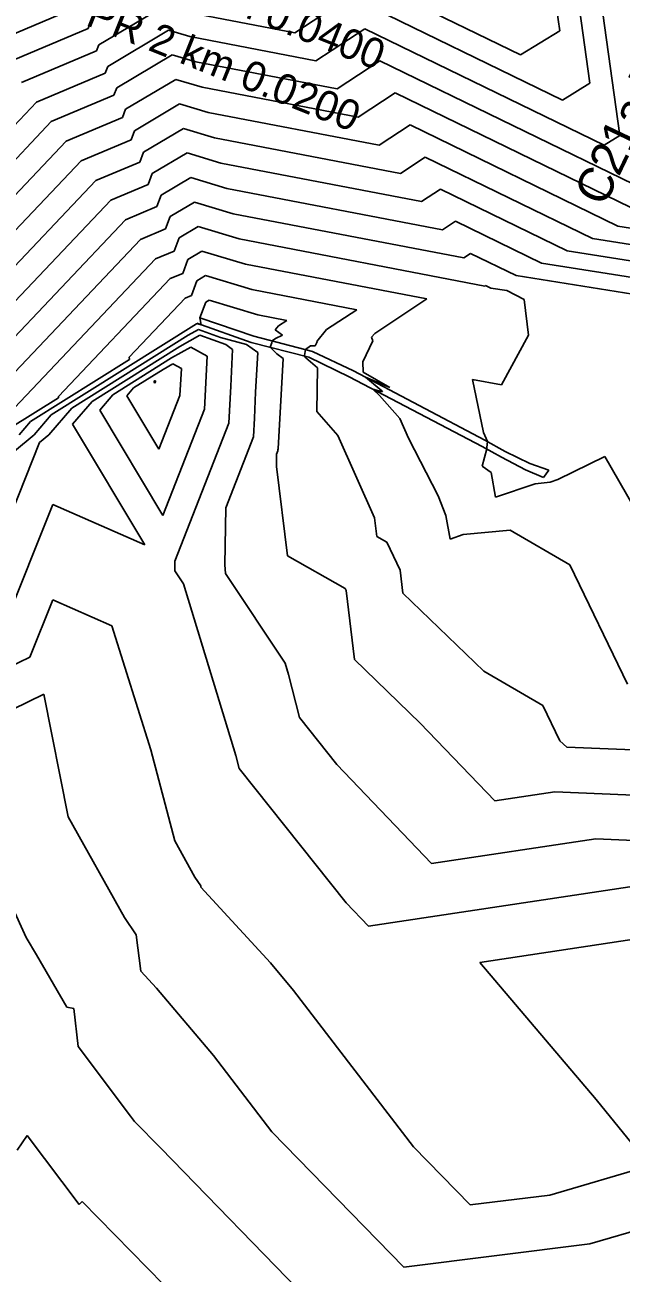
# Model space of a CAD drawing. Extents: x -549394 to -546608, y -1037055 to -1033629.
# Drawn here: x -548647.4 to -548467.8, y -1034298.9 to -1033923 of the extents above; entities that cross this region are included whole.
import ezdxf

# ---------------------------------------------------------------- set-up
doc = ezdxf.new("R2010")
doc.units = 0
for name, color, linetype in [('HLAVNI_VRST', 7, 'Continuous'), ('HRANA_L', 7, 'Continuous'), ('NORM_VRST', 7, 'Continuous'), ('x_popis_pricne_rezy_C21a', 7, 'Continuous'), ('x_popis_velky_C21a', 7, 'Continuous')]:
    doc.layers.add(name, color=color, linetype=linetype)

msp = doc.modelspace()

# ---------------------------------------------------------------- linework, layer by layer
at = {"layer": 'HLAVNI_VRST'}
for p, q in [((-548490.833895, -1033892.034012), (-548486.312771, -1033924.790682)), ((-548498.073314, -1033932.014031), (-548554.071999, -1033904.761011)), ((-548628.373693, -1033924.063589), (-548652.864545, -1033934.367749)), ((-548627.803158, -1033922.533449), (-548628.373693, -1033924.063589)), ((-548486.312771, -1033924.790682), (-548498.073314, -1033932.014031)), ((-548600.783034, -1033946.756375), (-548614.382105, -1033954.829188)), ((-548592.148146, -1033949.352685), (-548600.783034, -1033946.756375)), ((-548540.655675, -1033959.222434), (-548592.148146, -1033949.352685)), ((-548531.351368, -1033953.107008), (-548540.655675, -1033959.222434)), ((-548468.798144, -1033983.549941), (-548531.351368, -1033953.107008)), ((-548615.406888, -1033957.577593), (-548630.478182, -1033963.918615)), ((-548614.382105, -1033954.829188), (-548615.406888, -1033957.577593)), ((-548630.478182, -1033963.918615), (-548664.244255, -1033999.570355)), ((-548595.204583, -1033983.707716), (-548600.961053, -1033987.124927)), ((-548582.805577, -1033987.435809), (-548595.204583, -1033983.707716)), ((-548451.078973, -1033986.353764), (-548468.798144, -1033983.549941)), ((-548600.961053, -1033987.124927), (-548602.440083, -1033991.091598)), ((-548508.866518, -1034001.607976), (-548582.805577, -1033987.435809)), ((-548602.440083, -1033991.091598), (-548608.091818, -1033993.469481)), ((-548608.091818, -1033993.469481), (-548657.96766, -1034046.130638)), ((-548508.630736, -1034001.453004), (-548508.866518, -1034001.607976)), ((-548507.045567, -1034002.224462), (-548508.630736, -1034001.453004)), ((-548502.274967, -1034002.979346), (-548507.045567, -1034002.224462)), ((-548497.028333, -1034005.698333), (-548502.274967, -1034002.979346)), ((-548495.743902, -1034016.375854), (-548497.028333, -1034005.698333)), ((-548594.7162, -1034016.4408), (-548600.730965, -1034019.837795)), ((-548586.903582, -1034019.268358), (-548594.7162, -1034016.4408)), ((-548503.801111, -1034031.374444), (-548495.743902, -1034016.375854)), ((-548600.730965, -1034019.837795), (-548627.097363, -1034036.364388)), ((-548584.852373, -1034020.685085), (-548586.903582, -1034019.268358)), ((-548585.343887, -1034031.766844), (-548584.852373, -1034020.685085)), ((-548512.553077, -1034029.728974), (-548503.801111, -1034031.374444)), ((-548509.28, -1034045.683636), (-548512.553077, -1034029.728974)), ((-548585.938839, -1034042.902776), (-548585.343887, -1034031.766844)), ((-548627.097363, -1034036.364388), (-548633.015452, -1034043.246436)), ((-548633.015452, -1034043.246436), (-548611.262444, -1034079.530111)), ((-548602.206396, -1034084.51009), (-548585.938839, -1034042.902776)), ((-548508.10875, -1034048.48), (-548509.28, -1034045.683636)), ((-548508.307586, -1034050.197011), (-548508.10875, -1034048.48)), ((-548509.678349, -1034055.82422), (-548508.271111, -1034050.669722)), ((-548508.271111, -1034050.669722), (-548508.307586, -1034050.197011)), ((-548506.9755, -1034057.765), (-548509.678349, -1034055.82422)), ((-548472.695765, -1034052.912118), (-548486.924615, -1034059.835769)), ((-548457.036154, -1034080.402051), (-548472.695765, -1034052.912118)), ((-548505.662222, -1034065.251111), (-548506.9755, -1034057.765)), ((-548486.924615, -1034059.835769), (-548489.156957, -1034060.703478)), ((-548493.745556, -1034061.14), (-548505.662222, -1034065.251111)), ((-548489.156957, -1034060.703478), (-548493.745556, -1034061.14)), ((-548638.983878, -1034067.36403), (-548653.489501, -1034103.858004)), ((-548611.262444, -1034079.530111), (-548638.983878, -1034067.36403)), ((-548602.244378, -1034087.013838), (-548602.206396, -1034084.51009)), ((-548602.220848, -1034087.383939), (-548602.244378, -1034087.013838)), ((-548599.614032, -1034091.312177), (-548602.220848, -1034087.383939)), ((-548583.865933, -1034143.0094), (-548599.614032, -1034091.312177)), ((-548582.86797, -1034146.920305), (-548583.865933, -1034143.0094)), ((-548550.63627, -1034187.342378), (-548582.86797, -1034146.920305)), ((-548463.15334, -1034182.22053), (-548543.89, -1034194.389343)), ((-548543.89, -1034194.389343), (-548550.63627, -1034187.342378))]:
    msp.add_line(p, q, dxfattribs=at)
at = {"layer": 'HRANA_L'}
for p, q in [((-548579.25, -1034018.6), (-548595.61, -1034012.8)), ((-548594.66, -1034011.2), (-548578.47, -1034016.69)), ((-548578.47, -1034016.69), (-548560.81, -1034021.29)), ((-548561.83, -1034023.04), (-548579.25, -1034018.6)), ((-548548.37, -1034027.11), (-548560.81, -1034021.29)), ((-548549.74, -1034028.97), (-548561.83, -1034023.04)), ((-548549.74, -1034028.97), (-548509.65, -1034049.9)), ((-548508.87, -1034048.06), (-548548.37, -1034027.11)), ((-548508.87, -1034048.06), (-548502.78, -1034051.42)), ((-548503.81, -1034053.16), (-548509.65, -1034049.9)), ((-548502.78, -1034051.42), (-548495.34, -1034055.08)), ((-548496.63, -1034056.94), (-548503.81, -1034053.16)), ((-548495.34, -1034055.08), (-548489.59, -1034057.06)), ((-548491.15, -1034059.3), (-548496.63, -1034056.94)), ((-548489.59, -1034057.06), (-548491.15, -1034059.3))]:
    msp.add_line(p, q, dxfattribs=at)
at = {"layer": 'NORM_VRST'}
for p, q in [((-548482.367044, -1033903.57614), (-548477.267031, -1033940.527004)), ((-548549.527873, -1033914.43021), (-548566.087, -1033925.314)), ((-548485.506453, -1033945.587674), (-548549.527873, -1033914.43021)), ((-548473.900193, -1033915.118267), (-548468.221291, -1033956.263327)), ((-548630.967054, -1033917.360788), (-548657.341818, -1033928.457576)), ((-548605.245794, -1033917.195303), (-548625.118947, -1033928.992596)), ((-548566.087, -1033925.314), (-548599.622202, -1033918.886186)), ((-548544.983746, -1033924.09941), (-548559.729169, -1033933.791108)), ((-548472.939593, -1033959.161318), (-548544.983746, -1033924.09941)), ((-548604.130104, -1033924.585571), (-548622.434737, -1033935.451744)), ((-548597.753688, -1033926.502811), (-548604.130104, -1033924.585571)), ((-548559.729169, -1033933.791108), (-548597.753688, -1033926.502811)), ((-548625.780332, -1033930.76639), (-548648.387273, -1033940.277922)), ((-548625.118947, -1033928.992596), (-548625.780332, -1033930.76639)), ((-548603.014414, -1033931.975839), (-548619.750526, -1033941.910892)), ((-548595.885174, -1033934.119436), (-548603.014414, -1033931.975839)), ((-548622.434737, -1033935.451744), (-548623.186971, -1033937.469191)), ((-548553.371337, -1033942.268217), (-548595.885174, -1033934.119436)), ((-548540.43962, -1033933.768609), (-548553.371337, -1033942.268217)), ((-548460.372733, -1033972.734961), (-548540.43962, -1033933.768609)), ((-548623.186971, -1033937.469191), (-548643.91, -1033946.188095)), ((-548601.898724, -1033939.366107), (-548617.066316, -1033948.37004)), ((-548594.01666, -1033941.73606), (-548601.898724, -1033939.366107)), ((-548619.750526, -1033941.910892), (-548620.59361, -1033944.171992)), ((-548547.013506, -1033950.745325), (-548594.01666, -1033941.73606)), ((-548477.267031, -1033940.527004), (-548485.506453, -1033945.587674)), ((-548643.91, -1033946.188095), (-548668.010213, -1033971.634184)), ((-548620.59361, -1033944.171992), (-548639.432727, -1033952.098268)), ((-548535.895494, -1033943.437808), (-548547.013506, -1033950.745325)), ((-548461.14866, -1033979.815037), (-548535.895494, -1033943.437808)), ((-548617.066316, -1033948.37004), (-548618.000249, -1033950.874793)), ((-548639.432727, -1033952.098268), (-548666.754894, -1033980.946241)), ((-548618.000249, -1033950.874793), (-548634.955455, -1033958.008442)), ((-548599.667344, -1033954.146643), (-548611.697895, -1033961.288336)), ((-548590.279632, -1033956.96931), (-548599.667344, -1033954.146643)), ((-548634.955455, -1033958.008442), (-548665.499574, -1033990.258298)), ((-548534.297843, -1033967.699542), (-548590.279632, -1033956.96931)), ((-548468.221291, -1033956.263327), (-548472.939593, -1033959.161318)), ((-548611.697895, -1033961.288336), (-548612.813527, -1033964.280394)), ((-548598.551653, -1033961.536912), (-548609.013684, -1033967.747484)), ((-548588.411118, -1033964.585935), (-548598.551653, -1033961.536912)), ((-548612.813527, -1033964.280394), (-548626.000909, -1033969.828788)), ((-548527.940012, -1033976.176651), (-548588.411118, -1033964.585935)), ((-548526.807241, -1033962.776207), (-548534.297843, -1033967.699542)), ((-548476.447629, -1033987.284845), (-548526.807241, -1033962.776207)), ((-548609.013684, -1033967.747484), (-548610.220166, -1033970.983195)), ((-548597.435963, -1033968.92718), (-548606.329474, -1033974.206632)), ((-548586.542605, -1033972.202559), (-548597.435963, -1033968.92718)), ((-548626.000909, -1033969.828788), (-548662.988936, -1034008.882411)), ((-548610.220166, -1033970.983195), (-548621.523636, -1033975.738961)), ((-548521.582181, -1033984.653759), (-548586.542605, -1033972.202559)), ((-548522.263115, -1033972.445406), (-548527.940012, -1033976.176651)), ((-548484.097113, -1033991.01975), (-548522.263115, -1033972.445406)), ((-548621.523636, -1033975.738961), (-548661.733617, -1034018.194468)), ((-548606.329474, -1033974.206632), (-548607.626805, -1033977.685996)), ((-548596.320273, -1033976.317448), (-548603.645263, -1033980.665779)), ((-548584.674091, -1033979.819184), (-548596.320273, -1033976.317448)), ((-548607.626805, -1033977.685996), (-548617.046364, -1033981.649134)), ((-548603.645263, -1033980.665779), (-548605.033444, -1033984.388797)), ((-548515.224349, -1033993.130867), (-548584.674091, -1033979.819184)), ((-548617.046364, -1033981.649134), (-548660.478298, -1034027.506525)), ((-548605.033444, -1033984.388797), (-548612.569091, -1033987.559307)), ((-548517.718989, -1033982.114605), (-548521.582181, -1033984.653759)), ((-548491.746598, -1033994.754654), (-548517.718989, -1033982.114605)), ((-548612.569091, -1033987.559307), (-548659.222979, -1034036.818582)), ((-548448.054259, -1033991.777719), (-548476.447629, -1033987.284845)), ((-548594.088893, -1033991.097984), (-548598.276842, -1033993.584075)), ((-548580.937063, -1033995.052433), (-548594.088893, -1033991.097984)), ((-548513.174863, -1033991.783805), (-548515.224349, -1033993.130867)), ((-548499.396082, -1033998.489558), (-548513.174863, -1033991.783805)), ((-548445.029544, -1033997.201673), (-548484.097113, -1033991.01975)), ((-548598.276842, -1033993.584075), (-548599.846722, -1033997.794398)), ((-548526.363538, -1034005.512738), (-548580.937063, -1033995.052433)), ((-548442.004829, -1034002.625627), (-548491.746598, -1033994.754654)), ((-548603.614545, -1033999.379654), (-548637.266061, -1034034.910438)), ((-548599.846722, -1033997.794398), (-548603.614545, -1033999.379654)), ((-548592.973203, -1033998.488252), (-548595.592632, -1034000.043223)), ((-548579.068549, -1034002.669058), (-548592.973203, -1033998.488252)), ((-548457.928562, -1034005.051242), (-548499.396082, -1033998.489558)), ((-548595.592632, -1034000.043223), (-548597.253361, -1034004.497199)), ((-548547.425077, -1034008.734277), (-548579.068549, -1034002.669058)), ((-548599.137273, -1034005.289827), (-548615.96303, -1034023.055219)), ((-548597.253361, -1034004.497199), (-548599.137273, -1034005.289827)), ((-548592.908421, -1034006.502371), (-548594.66, -1034011.2)), ((-548591.857512, -1034005.87852), (-548592.908421, -1034006.502371)), ((-548577.200035, -1034010.285683), (-548591.857512, -1034005.87852)), ((-548542.043074, -1034015.879576), (-548526.363538, -1034005.512738)), ((-548568.486615, -1034011.955815), (-548577.200035, -1034010.285683)), ((-548556.516572, -1034014.7453), (-548547.425077, -1034008.734277)), ((-548595.734902, -1034012.971654), (-548639.504863, -1034040.406888)), ((-548595.1522, -1034014.6648), (-548598.232933, -1034016.404724)), ((-548595.5882, -1034012.8888), (-548595.734902, -1034012.971654)), ((-548595.270383, -1034013.003825), (-548595.5882, -1034012.8888)), ((-548594.269016, -1034013.27541), (-548595.270383, -1034013.003825)), ((-548588.478033, -1034017.080328), (-548595.1522, -1034014.6648)), ((-548594.66, -1034011.2), (-548594.269016, -1034013.27541)), ((-548594.66, -1034011.2), (-548594.66, -1034011.2)), ((-548594.66, -1034011.2), (-548594.66, -1034011.2)), ((-548594.66, -1034011.2), (-548594.66, -1034011.2)), ((-548594.66, -1034011.2), (-548594.66, -1034011.2)), ((-548594.66, -1034011.2), (-548594.66, -1034011.2)), ((-548571.972903, -1034014.798065), (-548570.990071, -1034013.611025)), ((-548570.990071, -1034013.611025), (-548568.486615, -1034011.955815)), ((-548559.441321, -1034018.277736), (-548556.516572, -1034014.7453)), ((-548598.232933, -1034016.404724), (-548633.301113, -1034038.385638)), ((-548580.667377, -1034019.198689), (-548588.478033, -1034017.080328)), ((-548573.054615, -1034018.756568), (-548572.919714, -1034018.135714)), ((-548572.919714, -1034018.135714), (-548571.948014, -1034017.380426)), ((-548569.819136, -1034016.368395), (-548571.972903, -1034014.798065)), ((-548571.948014, -1034017.380426), (-548569.819136, -1034016.368395)), ((-548559.966, -1034019.613333), (-548559.396963, -1034018.420593)), ((-548559.396963, -1034018.420593), (-548559.441321, -1034018.277736)), ((-548545.577, -1034024.401), (-548542.589556, -1034018.139111)), ((-548542.950755, -1034016.975849), (-548542.043074, -1034015.879576)), ((-548542.589556, -1034018.139111), (-548542.950755, -1034016.975849)), ((-548597.457597, -1034020.011318), (-548603.228996, -1034023.270866)), ((-548592.462077, -1034022.688792), (-548597.457597, -1034020.011318)), ((-548577.223636, -1034021.648325), (-548580.667377, -1034019.198689)), ((-548577.907541, -1034033.562623), (-548577.223636, -1034021.648325)), ((-548573.511647, -1034020.062588), (-548573.054615, -1034018.756568)), ((-548571.506552, -1034022.062989), (-548573.511647, -1034020.062588)), ((-548569.587273, -1034023.42823), (-548571.506552, -1034022.062989)), ((-548563.208462, -1034022.513964), (-548562.828286, -1034020.764286)), ((-548562.828286, -1034020.764286), (-548561.362941, -1034019.625294)), ((-548561.362941, -1034019.625294), (-548559.966, -1034019.613333)), ((-548615.885342, -1034023.73476), (-548645.708613, -1034042.428138)), ((-548603.228996, -1034023.270866), (-548620.893613, -1034034.343138)), ((-548615.96303, -1034023.055219), (-548615.885342, -1034023.73476)), ((-548602.798682, -1034025.050078), (-548605.727028, -1034026.703937)), ((-548600.26401, -1034026.408599), (-548602.798682, -1034025.050078)), ((-548593.31876, -1034038.723642), (-548592.462077, -1034022.688792)), ((-548571.147978, -1034050.617268), (-548569.587273, -1034023.42823)), ((-548563.264588, -1034022.674353), (-548563.208462, -1034022.513964)), ((-548562.739157, -1034023.198554), (-548563.264588, -1034022.674353)), ((-548559.23245, -1034026.260199), (-548562.739157, -1034023.198554)), ((-548545.481818, -1034027.584545), (-548545.577, -1034024.401)), ((-548605.727028, -1034026.703937), (-548614.689863, -1034032.321888)), ((-548600.698681, -1034034.544508), (-548600.26401, -1034026.408599)), ((-548559.501243, -1034039.393729), (-548559.23245, -1034026.260199)), ((-548537.43, -1034032.21), (-548545.481818, -1034027.584545)), ((-548539.857, -1034033.138), (-548544.779091, -1034029.014545)), ((-548544.779091, -1034029.014545), (-548537.43, -1034032.21)), ((-548614.689863, -1034032.321888), (-548616.701622, -1034034.66133)), ((-548608.486113, -1034030.300638), (-548608.544707, -1034030.368777)), ((-548608.544707, -1034030.368777), (-548608.263392, -1034030.838007)), ((-548608.225059, -1034030.137008), (-548608.486113, -1034030.300638)), ((-548608.263392, -1034030.838007), (-548608.078602, -1034030.365374)), ((-548608.139767, -1034030.088837), (-548608.225059, -1034030.137008)), ((-548608.065942, -1034030.128406), (-548608.139767, -1034030.088837)), ((-548608.078602, -1034030.365374), (-548608.065942, -1034030.128406)), ((-548578.254186, -1034041.37814), (-548577.907541, -1034033.562623)), ((-548540.574595, -1034034.598649), (-548542.595248, -1034032.700099)), ((-548542.595248, -1034032.700099), (-548539.68172, -1034033.460645)), ((-548539.68172, -1034033.460645), (-548539.857, -1034033.138)), ((-548537.43, -1034032.21), (-548537.43, -1034032.21)), ((-548537.43, -1034032.21), (-548537.43, -1034032.21)), ((-548537.43, -1034032.21), (-548537.43, -1034032.21)), ((-548537.43, -1034032.21), (-548537.43, -1034032.21)), ((-548637.227808, -1034035.245034), (-548651.912363, -1034044.449387)), ((-548637.266061, -1034034.910438), (-548637.227808, -1034035.245034)), ((-548620.893613, -1034034.343138), (-548624.858537, -1034038.953883)), ((-548616.701622, -1034034.66133), (-548607.043112, -1034050.771573)), ((-548607.043112, -1034050.771573), (-548600.698681, -1034034.544508)), ((-548534.443411, -1034041.510421), (-548540.574595, -1034034.598649)), ((-548639.504863, -1034040.406888), (-548644.649057, -1034046.388986)), ((-548633.301113, -1034038.385638), (-548640.177358, -1034046.38191)), ((-548624.858537, -1034038.953883), (-548605.822832, -1034070.70514)), ((-548605.822832, -1034070.70514), (-548593.31876, -1034038.723642)), ((-548553.092944, -1034046.617897), (-548559.501243, -1034039.393729)), ((-548645.708613, -1034042.428138), (-548649.120755, -1034046.396061)), ((-548578.558917, -1034047.081909), (-548578.254186, -1034041.37814)), ((-548531.830612, -1034047.387755), (-548534.443411, -1034041.510421)), ((-548644.649057, -1034046.388986), (-548657.814424, -1034057.344029)), ((-548640.177358, -1034046.38191), (-548642.976295, -1034048.710935)), ((-548586.891081, -1034068.392973), (-548578.558917, -1034047.081909)), ((-548542.056121, -1034071.444569), (-548553.092944, -1034046.617897)), ((-548522.89568, -1034064.85056), (-548531.830612, -1034047.387755)), ((-548642.976295, -1034048.710935), (-548661.105028, -1034094.320111)), ((-548571.631622, -1034055.957838), (-548571.575766, -1034052.275856)), ((-548571.575766, -1034052.275856), (-548571.178996, -1034051.261043)), ((-548571.178996, -1034051.261043), (-548571.164485, -1034050.989435)), ((-548571.164485, -1034050.989435), (-548571.147978, -1034050.617268)), ((-548568.275098, -1034082.835294), (-548571.631622, -1034055.957838)), ((-548520.591042, -1034070.754583), (-548522.89568, -1034064.85056)), ((-548587.152486, -1034085.624649), (-548586.891081, -1034068.392973)), ((-548519.347407, -1034077.843704), (-548520.591042, -1034070.754583)), ((-548541.353529, -1034077.070588), (-548542.056121, -1034071.444569)), ((-548538.348605, -1034078.778837), (-548541.353529, -1034077.070588)), ((-548515.375185, -1034076.473333), (-548519.347407, -1034077.843704)), ((-548501.19, -1034075.123871), (-548515.375185, -1034076.473333)), ((-548483.218324, -1034085.595027), (-548501.19, -1034075.123871)), ((-548534.348228, -1034087.193797), (-548538.348605, -1034078.778837)), ((-548586.990545, -1034088.171818), (-548587.152486, -1034085.624649)), ((-548550.961008, -1034092.678062), (-548568.275098, -1034082.835294)), ((-548465.868146, -1034121.489536), (-548483.218324, -1034085.595027)), ((-548569.049516, -1034115.207339), (-548586.990545, -1034088.171818)), ((-548533.511429, -1034094.134898), (-548534.348228, -1034087.193797)), ((-548550.664684, -1034093.301392), (-548550.961008, -1034092.678062)), ((-548548.154286, -1034114.124694), (-548550.664684, -1034093.301392)), ((-548639.00289, -1034096.109278), (-548645.873974, -1034113.395896)), ((-548621.22289, -1034103.91237), (-548639.00289, -1034096.109278)), ((-548509.168261, -1034117.64), (-548533.511429, -1034094.134898)), ((-548609.424082, -1034141.284082), (-548621.22289, -1034103.91237)), ((-548645.873974, -1034113.395896), (-548670.80904, -1034125.463437)), ((-548568.019267, -1034118.5894), (-548569.049516, -1034115.207339)), ((-548528.342692, -1034133.254231), (-548548.154286, -1034114.124694)), ((-548564.700457, -1034131.595431), (-548568.019267, -1034118.5894)), ((-548491.42373, -1034127.978811), (-548509.168261, -1034117.64)), ((-548641.66, -1034124.58), (-548668.722353, -1034137.677059)), ((-548634.40326, -1034161.462044), (-548641.66, -1034124.58)), ((-548486.291987, -1034138.595497), (-548491.42373, -1034127.978811)), ((-548553.398432, -1034145.769405), (-548564.700457, -1034131.595431)), ((-548505.89, -1034156.707682), (-548528.342692, -1034133.254231)), ((-548484.158636, -1034140.506818), (-548486.291987, -1034138.595497)), ((-548602.280704, -1034168.747465), (-548609.424082, -1034141.284082)), ((-548422.375745, -1034143.071602), (-548484.158636, -1034140.506818)), ((-548524.89, -1034175.548512), (-548553.398432, -1034145.769405)), ((-548647.017907, -1034197.785814), (-548667.921356, -1034152.071525)), ((-548487.739898, -1034153.972057), (-548505.89, -1034156.707682)), ((-548424.65234, -1034156.591001), (-548487.739898, -1034153.972057)), ((-548617.382208, -1034191.767403), (-548634.40326, -1034161.462044)), ((-548596.185556, -1034179.637778), (-548602.280704, -1034168.747465)), ((-548475.446619, -1034168.096293), (-548524.89, -1034175.548512)), ((-548426.928936, -1034170.110401), (-548475.446619, -1034168.096293)), ((-548594.407674, -1034182.26907), (-548596.185556, -1034179.637778)), ((-548594.355113, -1034182.69203), (-548594.407674, -1034182.26907)), ((-548573.46303, -1034205.492121), (-548594.355113, -1034182.69203)), ((-548613.849535, -1034196.995814), (-548617.382208, -1034191.767403)), ((-548643.929429, -1034203.011524), (-548647.017907, -1034197.785814)), ((-548612.482932, -1034207.992782), (-548613.849535, -1034196.995814)), ((-548450.860061, -1034196.344766), (-548510.405594, -1034205.319604)), ((-548634.8, -1034218.773333), (-548643.929429, -1034203.011524)), ((-548566.447159, -1034213.77125), (-548573.46303, -1034205.492121)), ((-548510.405594, -1034205.319604), (-548475.28601, -1034246.589615)), ((-548607.786263, -1034213.118384), (-548612.482932, -1034207.992782)), ((-548590.602462, -1034233.39625), (-548607.786263, -1034213.118384)), ((-548530.299444, -1034260.916111), (-548566.447159, -1034213.77125)), ((-548632.629216, -1034219.173137), (-548634.8, -1034218.773333)), ((-548631.360922, -1034230.662979), (-548632.629216, -1034219.173137)), ((-548615.632667, -1034251.622667), (-548631.360922, -1034230.662979)), ((-548572.992037, -1034256.364259), (-548590.602462, -1034233.39625)), ((-548475.28601, -1034246.589615), (-548459.160435, -1034266.605362)), ((-548614.383594, -1034253.288828), (-548615.632667, -1034251.622667)), ((-548614.338015, -1034253.244682), (-548614.383594, -1034253.288828)), ((-548606.489474, -1034261.257105), (-548614.338015, -1034253.244682)), ((-548646.686133, -1034257.415359), (-548649.696939, -1034261.881939)), ((-548631.055469, -1034278.265391), (-548646.686133, -1034257.415359)), ((-548533.285682, -1034297.148182), (-548572.992037, -1034256.364259)), ((-548553.288929, -1034315.901429), (-548606.489474, -1034261.257105)), ((-548513.282435, -1034278.394935), (-548530.299444, -1034260.916111)), ((-548459.160435, -1034266.605362), (-548489.245278, -1034275.387292)), ((-548407.001014, -1034269.639179), (-548477.198981, -1034290.130347)), ((-548630.098315, -1034277.338315), (-548631.055469, -1034278.265391)), ((-548587.901266, -1034320.416463), (-548630.098315, -1034277.338315)), ((-548489.245278, -1034275.387292), (-548513.282435, -1034278.394935)), ((-548477.198981, -1034290.130347), (-548533.285682, -1034297.148182))]:
    msp.add_line(p, q, dxfattribs=at)

# ---------------------------------------------------------------- texts
at = {"layer": 'x_popis_pricne_rezy_C21a'}
for s, p in [('PŘ 3 km 0.0400', (-548621.947956, -1033904.324145)), ('PŘ 2 km 0.0200', (-548629.407275, -1033922.881046))]:
    msp.add_text(s, height=9.06272, rotation=338.101349, dxfattribs=at).set_placement(p)
at = {"layer": 'x_popis_velky_C21a'}
msp.add_text('C21a,P4/30', height=10.5, rotation=64.473381, dxfattribs=at).set_placement((-548472.859288, -1033978.068494))

doc.saveas('drawing.dxf')
